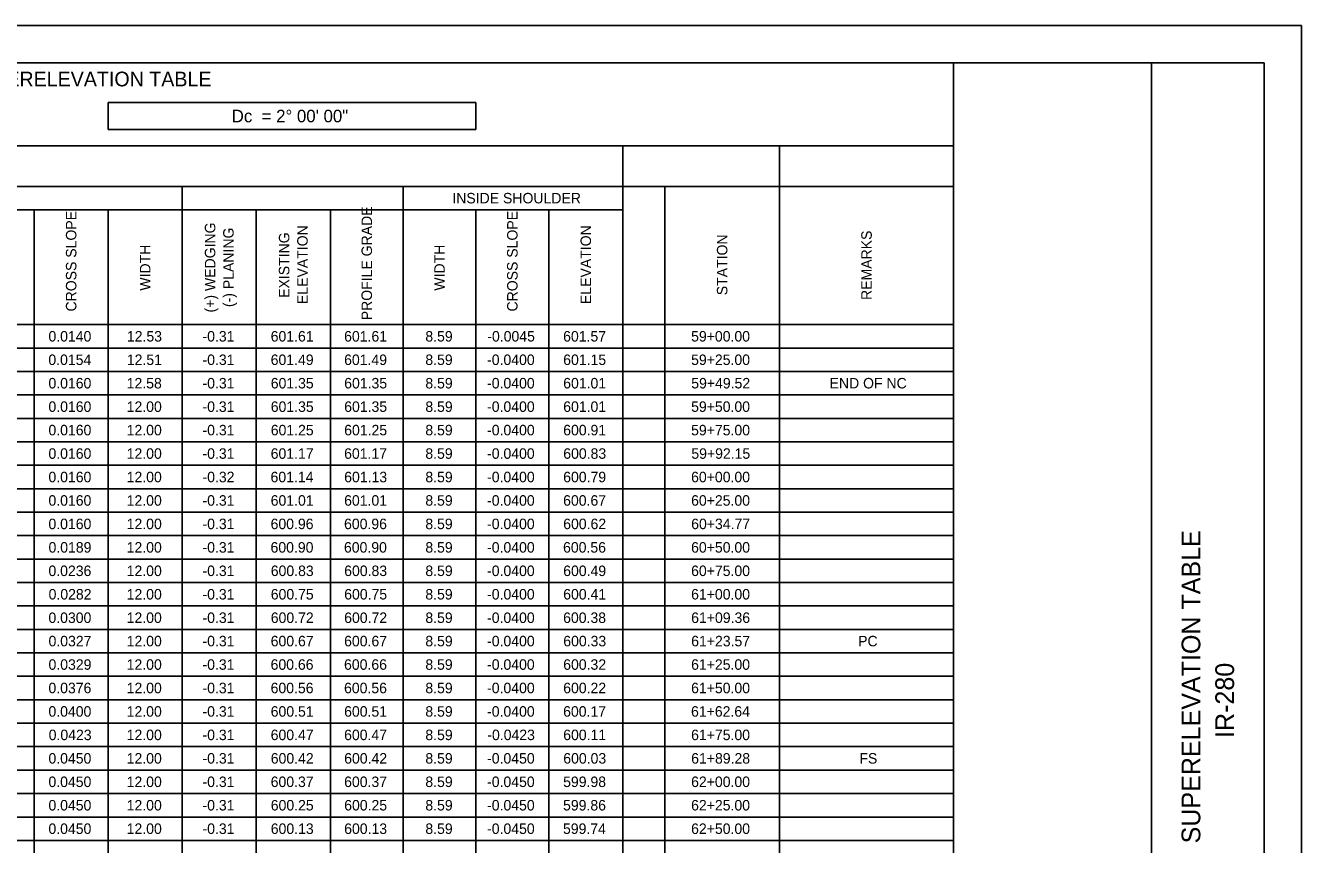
# Model space of a CAD drawing. Extents: x 0 to 34, y 0 to 22.
# Drawn here: x 16.97 to 34, y 11.07 to 22 of the extents above; entities that cross this region are included whole.
import ezdxf

# ---------------------------------------------------------------- set-up
doc = ezdxf.new("R2010")
doc.units = 0
for name, color, linetype in [('SH_Border', 7, 'Continuous'), ('SH_Cut_Line', 7, 'Continuous'), ('SH_Data', 7, 'Continuous'), ('SH_Text', 7, 'Continuous')]:
    doc.layers.add(name, color=color, linetype=linetype)

msp = doc.modelspace()

# ---------------------------------------------------------------- linework, layer by layer
at = {"layer": 'SH_Border'}
msp.add_line((32, 0.5), (32, 21.5), dxfattribs=at)
msp.add_lwpolyline([(1.5, 21.5), (33.5, 21.5), (33.5, 0.5), (1.5, 0.5)], close=True, dxfattribs=at)
at = {"layer": 'SH_Cut_Line'}
msp.add_lwpolyline([(0, 0), (34, 0), (34, 22), (0, 22)], close=True, dxfattribs=at)
at = {"layer": 'SH_Text'}
for p, q in [((4.14, 21.5), (29.356, 21.5)), ((29.356, 21.5), (29.356, 0.484)), ((18.074, 20.973), (22.982, 20.973)), ((18.074, 20.973), (18.074, 20.611)), ((22.982, 20.973), (22.982, 20.611)), ((18.074, 20.611), (22.982, 20.611)), ((4.14, 20.396), (29.356, 20.396)), ((24.942, 20.396), (24.942, 0.484)), ((27.034, 20.396), (27.034, 0.484)), ((4.14, 19.853), (29.356, 19.853)), ((19.062, 19.853), (19.062, 0.484)), ((22.011, 19.853), (22.011, 0.484)), ((25.502, 19.853), (25.502, 0.484)), ((4.14, 19.54), (24.942, 19.54)), ((17.086, 19.54), (17.086, 0.484)), ((18.074, 19.54), (18.074, 0.484)), ((20.051, 19.54), (20.051, 0.484)), ((21.039, 19.54), (21.039, 0.484)), ((22.982, 19.54), (22.982, 0.484)), ((23.954, 19.54), (23.954, 0.484)), ((4.14, 18.008), (29.356, 18.008)), ((4.14, 17.695), (29.356, 17.695)), ((4.14, 17.382), (29.356, 17.382)), ((4.14, 17.069), (29.356, 17.069)), ((4.14, 16.756), (29.356, 16.756)), ((4.14, 16.444), (29.356, 16.444)), ((4.14, 16.131), (29.356, 16.131)), ((4.14, 15.818), (29.356, 15.818)), ((4.14, 15.505), (29.356, 15.505)), ((4.14, 15.192), (29.356, 15.192)), ((4.14, 14.879), (29.356, 14.879)), ((4.14, 14.566), (29.356, 14.566)), ((4.14, 14.253), (29.356, 14.253)), ((4.14, 13.94), (29.356, 13.94)), ((4.14, 13.627), (29.356, 13.627)), ((4.14, 13.314), (29.356, 13.314)), ((4.14, 13.001), (29.356, 13.001)), ((4.14, 12.688), (29.356, 12.688)), ((4.14, 12.375), (29.356, 12.375)), ((4.14, 12.062), (29.356, 12.062)), ((4.14, 11.749), (29.356, 11.749)), ((4.14, 11.436), (29.356, 11.436)), ((4.14, 11.124), (29.356, 11.124))]:
    msp.add_line(p, q, dxfattribs=at)

# ---------------------------------------------------------------- texts
at = {"layer": 'SH_Data'}
for s, p in [('SUPERELEVATION TABLE', (32.65, 11.084)), ('IR-280', (33.1, 12.491))]:
    msp.add_text(s, height=0.25, rotation=90, dxfattribs=at).set_placement(p)
at = {"layer": 'SH_Text'}
for s, height, p in [('WOO/LUC-280-06.20/00.00 - SUPERELEVATION TABLE', 0.196, (12.694, 21.188)), ('Dc  = 2° 00\' 00"', 0.168, (19.723, 20.708)), ('INSIDE SHOULDER', 0.14, (22.667, 19.626)), ('0.0140', 0.14, (17.277, 17.782)), ('12.53', 0.14, (18.324, 17.782)), ('-0.31', 0.14, (19.333, 17.782)), ('601.61', 0.14, (20.243, 17.782)), ('601.61', 0.14, (21.223, 17.782)), ('8.59', 0.14, (22.307, 17.782)), ('-0.0045', 0.14, (23.134, 17.782)), ('601.57', 0.14, (24.146, 17.782)), ('59+00.00', 0.14, (25.854, 17.782)), ('0.0154', 0.14, (17.276, 17.469)), ('12.51', 0.14, (18.323, 17.469)), ('-0.31', 0.14, (19.333, 17.469)), ('601.49', 0.14, (20.243, 17.469)), ('601.49', 0.14, (21.223, 17.469)), ('8.59', 0.14, (22.307, 17.469)), ('-0.0400', 0.14, (23.131, 17.469)), ('601.15', 0.14, (24.147, 17.469)), ('59+25.00', 0.14, (25.854, 17.469)), ('0.0160', 0.14, (17.277, 17.156)), ('12.58', 0.14, (18.321, 17.156)), ('-0.31', 0.14, (19.333, 17.156)), ('601.35', 0.14, (20.244, 17.156)), ('601.35', 0.14, (21.224, 17.156)), ('8.59', 0.14, (22.307, 17.156)), ('-0.0400', 0.14, (23.131, 17.156)), ('601.01', 0.14, (24.147, 17.156)), ('59+49.52', 0.14, (25.856, 17.156)), ('END OF NC', 0.14, (27.702, 17.156)), ('0.0160', 0.14, (17.277, 16.843)), ('12.00', 0.14, (18.321, 16.843)), ('-0.31', 0.14, (19.333, 16.843)), ('601.35', 0.14, (20.244, 16.843)), ('601.35', 0.14, (21.224, 16.843)), ('8.59', 0.14, (22.307, 16.843)), ('-0.0400', 0.14, (23.131, 16.843)), ('601.01', 0.14, (24.147, 16.843)), ('59+50.00', 0.14, (25.854, 16.843)), ('0.0160', 0.14, (17.277, 16.53)), ('12.00', 0.14, (18.321, 16.53)), ('-0.31', 0.14, (19.333, 16.53)), ('601.25', 0.14, (20.244, 16.53)), ('601.25', 0.14, (21.224, 16.53)), ('8.59', 0.14, (22.307, 16.53)), ('-0.0400', 0.14, (23.131, 16.53)), ('600.91', 0.14, (24.147, 16.53)), ('59+75.00', 0.14, (25.854, 16.53)), ('0.0160', 0.14, (17.277, 16.217)), ('12.00', 0.14, (18.321, 16.217)), ('-0.31', 0.14, (19.333, 16.217)), ('601.17', 0.14, (20.243, 16.217)), ('601.17', 0.14, (21.223, 16.217)), ('8.59', 0.14, (22.307, 16.217)), ('-0.0400', 0.14, (23.131, 16.217)), ('600.83', 0.14, (24.148, 16.217)), ('59+92.15', 0.14, (25.857, 16.217)), ('0.0160', 0.14, (17.277, 15.904)), ('12.00', 0.14, (18.321, 15.904)), ('-0.32', 0.14, (19.333, 15.904)), ('601.14', 0.14, (20.241, 15.904)), ('601.13', 0.14, (21.224, 15.904)), ('8.59', 0.14, (22.307, 15.904)), ('-0.0400', 0.14, (23.131, 15.904)), ('600.79', 0.14, (24.147, 15.904)), ('60+00.00', 0.14, (25.854, 15.904)), ('0.0160', 0.14, (17.277, 15.591)), ('12.00', 0.14, (18.321, 15.591)), ('-0.31', 0.14, (19.333, 15.591)), ('601.01', 0.14, (20.243, 15.591)), ('601.01', 0.14, (21.223, 15.591)), ('8.59', 0.14, (22.307, 15.591)), ('-0.0400', 0.14, (23.131, 15.591)), ('600.67', 0.14, (24.146, 15.591)), ('60+25.00', 0.14, (25.854, 15.591)), ('0.0160', 0.14, (17.277, 15.278)), ('12.00', 0.14, (18.321, 15.278)), ('-0.31', 0.14, (19.333, 15.278)), ('600.96', 0.14, (20.242, 15.278)), ('600.96', 0.14, (21.222, 15.278)), ('8.59', 0.14, (22.307, 15.278)), ('-0.0400', 0.14, (23.131, 15.278)), ('600.62', 0.14, (24.147, 15.278)), ('60+34.77', 0.14, (25.855, 15.278)), ('0.0189', 0.14, (17.278, 14.965)), ('12.00', 0.14, (18.321, 14.965)), ('-0.31', 0.14, (19.333, 14.965)), ('600.90', 0.14, (20.241, 14.965)), ('600.90', 0.14, (21.221, 14.965)), ('8.59', 0.14, (22.307, 14.965)), ('-0.0400', 0.14, (23.131, 14.965)), ('600.56', 0.14, (24.145, 14.965)), ('60+50.00', 0.14, (25.854, 14.965)), ('0.0236', 0.14, (17.277, 14.652)), ('12.00', 0.14, (18.321, 14.652)), ('-0.31', 0.14, (19.333, 14.652)), ('600.83', 0.14, (20.244, 14.652)), ('600.83', 0.14, (21.224, 14.652)), ('8.59', 0.14, (22.307, 14.652)), ('-0.0400', 0.14, (23.131, 14.652)), ('600.49', 0.14, (24.147, 14.652)), ('60+75.00', 0.14, (25.854, 14.652)), ('0.0282', 0.14, (17.279, 14.339)), ('12.00', 0.14, (18.321, 14.339)), ('-0.31', 0.14, (19.333, 14.339)), ('600.75', 0.14, (20.244, 14.339)), ('600.75', 0.14, (21.224, 14.339)), ('8.59', 0.14, (22.307, 14.339)), ('-0.0400', 0.14, (23.131, 14.339)), ('600.41', 0.14, (24.147, 14.339)), ('61+00.00', 0.14, (25.854, 14.339)), ('0.0300', 0.14, (17.277, 14.026)), ('12.00', 0.14, (18.321, 14.026)), ('-0.31', 0.14, (19.333, 14.026)), ('600.72', 0.14, (20.244, 14.026)), ('600.72', 0.14, (21.224, 14.026)), ('8.59', 0.14, (22.307, 14.026)), ('-0.0400', 0.14, (23.131, 14.026)), ('600.38', 0.14, (24.146, 14.026)), ('61+09.36', 0.14, (25.855, 14.026)), ('0.0327', 0.14, (17.278, 13.714)), ('12.00', 0.14, (18.321, 13.714)), ('-0.31', 0.14, (19.333, 13.714)), ('600.67', 0.14, (20.243, 13.714)), ('600.67', 0.14, (21.223, 13.714)), ('8.59', 0.14, (22.307, 13.714)), ('-0.0400', 0.14, (23.131, 13.714)), ('600.33', 0.14, (24.148, 13.714)), ('61+23.57', 0.14, (25.855, 13.714)), ('PC', 0.14, (28.083, 13.714)), ('0.0329', 0.14, (17.278, 13.401)), ('12.00', 0.14, (18.321, 13.401)), ('-0.31', 0.14, (19.333, 13.401)), ('600.66', 0.14, (20.242, 13.401)), ('600.66', 0.14, (21.222, 13.401)), ('8.59', 0.14, (22.307, 13.401)), ('-0.0400', 0.14, (23.131, 13.401)), ('600.32', 0.14, (24.147, 13.401)), ('61+25.00', 0.14, (25.854, 13.401)), ('0.0376', 0.14, (17.277, 13.088)), ('12.00', 0.14, (18.321, 13.088)), ('-0.31', 0.14, (19.333, 13.088)), ('600.56', 0.14, (20.242, 13.088)), ('600.56', 0.14, (21.222, 13.088)), ('8.59', 0.14, (22.307, 13.088)), ('-0.0400', 0.14, (23.131, 13.088)), ('600.22', 0.14, (24.147, 13.088)), ('61+50.00', 0.14, (25.854, 13.088)), ('0.0400', 0.14, (17.277, 12.775)), ('12.00', 0.14, (18.321, 12.775)), ('-0.31', 0.14, (19.333, 12.775)), ('600.51', 0.14, (20.243, 12.775)), ('600.51', 0.14, (21.223, 12.775)), ('8.59', 0.14, (22.307, 12.775)), ('-0.0400', 0.14, (23.131, 12.775)), ('600.17', 0.14, (24.146, 12.775)), ('61+62.64', 0.14, (25.853, 12.775)), ('0.0423', 0.14, (17.28, 12.462)), ('12.00', 0.14, (18.321, 12.462)), ('-0.31', 0.14, (19.333, 12.462)), ('600.47', 0.14, (20.243, 12.462)), ('600.47', 0.14, (21.223, 12.462)), ('8.59', 0.14, (22.307, 12.462)), ('-0.0423', 0.14, (23.134, 12.462)), ('600.11', 0.14, (24.147, 12.462)), ('61+75.00', 0.14, (25.854, 12.462)), ('0.0450', 0.14, (17.277, 12.149)), ('12.00', 0.14, (18.321, 12.149)), ('-0.31', 0.14, (19.333, 12.149)), ('600.42', 0.14, (20.244, 12.149)), ('600.42', 0.14, (21.224, 12.149)), ('8.59', 0.14, (22.307, 12.149)), ('-0.0450', 0.14, (23.131, 12.149)), ('600.03', 0.14, (24.148, 12.149)), ('61+89.28', 0.14, (25.855, 12.149)), ('FS', 0.14, (28.1, 12.149)), ('0.0450', 0.14, (17.277, 11.836)), ('12.00', 0.14, (18.321, 11.836)), ('-0.31', 0.14, (19.333, 11.836)), ('600.37', 0.14, (20.243, 11.836)), ('600.37', 0.14, (21.223, 11.836)), ('8.59', 0.14, (22.307, 11.836)), ('-0.0450', 0.14, (23.131, 11.836)), ('599.98', 0.14, (24.146, 11.836)), ('62+00.00', 0.14, (25.854, 11.836)), ('0.0450', 0.14, (17.277, 11.523)), ('12.00', 0.14, (18.321, 11.523)), ('-0.31', 0.14, (19.333, 11.523)), ('600.25', 0.14, (20.244, 11.523)), ('600.25', 0.14, (21.224, 11.523)), ('8.59', 0.14, (22.307, 11.523)), ('-0.0450', 0.14, (23.131, 11.523)), ('599.86', 0.14, (24.145, 11.523)), ('62+25.00', 0.14, (25.854, 11.523)), ('0.0450', 0.14, (17.277, 11.21)), ('12.00', 0.14, (18.321, 11.21)), ('-0.31', 0.14, (19.333, 11.21)), ('600.13', 0.14, (20.244, 11.21)), ('600.13', 0.14, (21.224, 11.21)), ('8.59', 0.14, (22.307, 11.21)), ('-0.0450', 0.14, (23.131, 11.21)), ('599.74', 0.14, (24.144, 11.21)), ('62+50.00', 0.14, (25.854, 11.21))]:
    msp.add_text(s, height=height, dxfattribs=at).set_placement(p)
for s, p in [('CROSS SLOPE', (17.65, 18.183)), ('PROFILE GRADE', (21.595, 18.066)), ('CROSS SLOPE', (23.538, 18.183)), ('(+) WEDGING', (19.504, 18.17)), ('(-) PLANING', (19.749, 18.242)), ('ELEVATION', (20.737, 18.283)), ('ELEVATION', (24.518, 18.283)), ('REMARKS', (28.265, 18.337)), ('EXISTING ', (20.492, 18.365)), ('STATION', (26.338, 18.4)), ('WIDTH', (18.638, 18.461)), ('WIDTH', (22.566, 18.461))]:
    msp.add_text(s, height=0.14, rotation=90, dxfattribs=at).set_placement(p)

doc.saveas('drawing.dxf')
